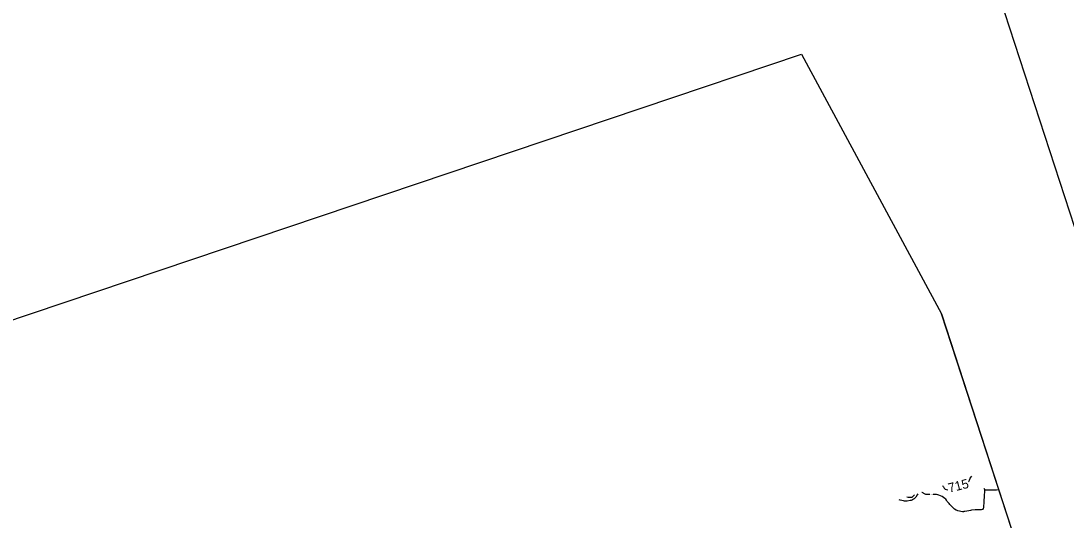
# Model space of a CAD drawing. Extents: x -468556195 to 3353078, y -306091294 to 1252632.
# Drawn here: x 1831176 to 1834891, y 535626 to 537403 of the extents above; entities that cross this region are included whole.
import ezdxf

# ---------------------------------------------------------------- set-up
doc = ezdxf.new("R2010")
doc.units = 0
for name, color, linetype in [('DT_X_Contour_Minor', 7, 'Continuous'), ('DT_X_Terrain_Ground_Line', 7, 'Continuous'), ('Level 19', 7, 'Continuous'), ('SC_Scratch1', 7, 'Continuous'), ('SH_Border', 7, 'Continuous')]:
    doc.layers.add(name, color=color, linetype=linetype)

msp = doc.modelspace()

# ---------------------------------------------------------------- linework, layer by layer
at = {"layer": 'DT_X_Contour_Minor'}
for points in [[(1834544.1, 535762.2), (1834544.9, 535763.3), (1834547.3, 535768), (1834550, 535775.4), (1834556, 535782.9)], [(1834451.8, 535749), (1834452.6, 535747.8), (1834454.6, 535744.4), (1834457.4, 535740.4), (1834460.9, 535737), (1834465.2, 535734.9), (1834470, 535733.9), (1834470.7, 535733.8)], [(1834364.3, 535720.5), (1834361.6, 535716.1), (1834356.2, 535708.5), (1834351.3, 535702.6), (1834348.8, 535700.7), (1834345.3, 535698.6), (1834340.4, 535696.8), (1834336.6, 535695.9), (1834326.3, 535693.7), (1834324.1, 535693.8), (1834322.2, 535693.9), (1834316.6, 535694), (1834313, 535694.6), (1834301, 535697.4), (1834296.9, 535698.6)], [(1834350.8, 535716.1), (1834350.5, 535715.6), (1834343.3, 535707.8), (1834341.9, 535707.3), (1834338, 535706.6), (1834333.5, 535706.3), (1834329.3, 535706.7), (1834325.2, 535707.8)], [(1834406.2, 535717.3), (1834400, 535717.4), (1834394.9, 535717.6), (1834392.4, 535718.1), (1834389.9, 535719), (1834378.8, 535724.3), (1834377.6, 535724.8)], [(1834651.7, 535734), (1834648.8, 535734), (1834643.4, 535733.2), (1834639.5, 535732.9), (1834631.5, 535733.1), (1834628.3, 535733.2), (1834605, 535732.6), (1834603.5, 535733), (1834602.8, 535733.9), (1834599.8, 535739.3), (1834600.4, 535734.7), (1834600.8, 535730.6), (1834600.1, 535712), (1834598.8, 535693.9), (1834596.6, 535670.5), (1834596.3, 535668), (1834595.6, 535665.9), (1834594.1, 535664.4), (1834592.6, 535663.7), (1834588.8, 535662.9), (1834584.7, 535662.8), (1834577, 535663.1), (1834574, 535663.3), (1834568.1, 535663.1), (1834554.2, 535661.9), (1834550.7, 535660.3), (1834545.3, 535659.1), (1834537.7, 535658.1), (1834530.8, 535657.6), (1834527.4, 535656.7), (1834525.7, 535655.8), (1834523.1, 535655.8), (1834516.9, 535656.8), (1834512, 535657.9), (1834506.3, 535659.6), (1834503.8, 535660.7), (1834500.3, 535662.3), (1834494.4, 535665.9), (1834489.4, 535669.8), (1834489, 535670.1), (1834484.3, 535674.5), (1834477.6, 535682.4), (1834474.9, 535685.5), (1834468.2, 535692.3), (1834465.9, 535697.4), (1834463.8, 535700.5), (1834460.2, 535703.7), (1834455.4, 535707), (1834449.9, 535710.1), (1834444.3, 535712.7), (1834438.9, 535714.8), (1834434.3, 535716.2), (1834430.6, 535717), (1834427.2, 535717.2), (1834418.2, 535717.3)]]:
    msp.add_lwpolyline(points, dxfattribs=at)
at = {"layer": 'DT_X_Terrain_Ground_Line'}
msp.add_line((1835055.9, 534489.2), (1834448.3, 536360.7), dxfattribs=at)
at = {"layer": 'SC_Scratch1'}
msp.add_lwpolyline([(1826839.3, 533890.1), (1826769.8, 534863.1), (1833950.4, 537284.3), (1834448.3, 536360.7), (1835055.9, 534489.2), (1835128.1, 533209.3), (1827818.5, 531160.4), (1827446.8, 532019.1)], close=True, dxfattribs=at)
at = {"layer": 'SH_Border'}
msp.add_line((1836175.1, 532806.4), (1834229.7, 538798.6), dxfattribs=at)

# ---------------------------------------------------------------- texts
at = {"layer": 'Level 19'}
for s, height, rotation, p in [('715', 33, 14.2437, (1834476, 535723.8)), ('714', 4, 359.7487, (1834407, 535715.3))]:
    msp.add_text(s, height=height, rotation=rotation, dxfattribs=at).set_placement(p)

doc.saveas('drawing.dxf')
